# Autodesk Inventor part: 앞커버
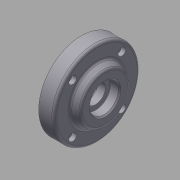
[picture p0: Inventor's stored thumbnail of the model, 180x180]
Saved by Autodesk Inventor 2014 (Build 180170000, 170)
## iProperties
Company: 한국ATC센터
Created: 2015-12
Part Number: 앞커버
Document SubType Name: Modeling
Designer: 앞커버
Density: 2.71 g/cm^3
Mass: 114.339 g
Surface Area: 117.889 cm^2
Volume: 42.1916 cm^3
Material: 알루미늄-6061
Appearance: 알루미늄 - 평지
Author: mdu
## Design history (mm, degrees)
sketch "스케치1"
  geometry: L1 (-11.5, 0)-(11.5, 0); L2 (11.5, 0)-(11.5, 22.5); L3 (11.5, 22.5)-(6.5, 22.5); L4 (6.5, 22.5)-(6.5, 32.5); L5 (6.5, 32.5)-(-5.5, 32.5); L6 (-5.5, 32.5)-(-5.5, 21); L7 (-5.5, 21)-(-11.5, 18.202); L8 (-11.5, 18.202)-(-11.5, 0); 2 further points
  constraints: 16 end point, 3 parallel, 3 perpendicular, 1 coincident, 1 horizontal, 1 midpoint
  dimensions: "d0" = 23 distance of L1.start L1.end; "d1" = 65 diameter of L5 L1; "d2" = 45 diameter of L3 L1; "d3" = 42 diameter of L6.end L1; "d4" = 115 deg angle of L7 L6; "d5" = 12 distance of L4.end L5.end; "d6" = 5 distance of L2.end L3.end
revolve "회전1" sketch "스케치1" stored, may be unused: angle "d7" = 90 deg
sketch "스케치2"
  geometry: L1 (0, 0)-(32.5, 0); L2 (0, 0)-(18.738, 18.738); 1 further point
  constraints: 4 end point, 1 horizontal, 1 horizontal alignment, 1 other
  dimensions: "d8" = 45 deg angle of L1 L2; "d9" = 26.5 distance of L1.start L2.end
hole "구멍1" sketch "스케치2" at (18.738, 18.738) diameter "d10" = 3.4; stored, may be unused: countersink angle "d14" = 90 deg, drill point angle "d16" = 118 deg; dims "d11" = 6, "d12" = 6, "d13" = 3.3, "d15" = 8
fillet "모깎기1" dims "d20" = 2
hole "구멍2" diameter "d23" = 15; stored, may be unused: countersink angle "d27" = 90 deg, drill point angle "d29" = 118 deg; dims "d21" = 10, "d22" = 10, "d24" = 6, "d25" = 32, "d26" = 10, "d28" = 8
hole "구멍3" diameter "d32" = 22; stored, may be unused: countersink angle "d36" = 90 deg, drill point angle "d38" = 0 deg; dims "d30" = 10, "d31" = 10, "d33" = 6, "d34" = 32, "d35" = 10, "d37" = 7.3
chamfer "모따기1" distance "d39" = 1; stored, may be unused: second distance "d40" = 2, angle "d41" = 45 deg
fillet "모깎기2" dims "d42" = 0.3
node "솔리드1"
pattern_circular "원형 패턴1" dims angle "d18" = 360 deg
